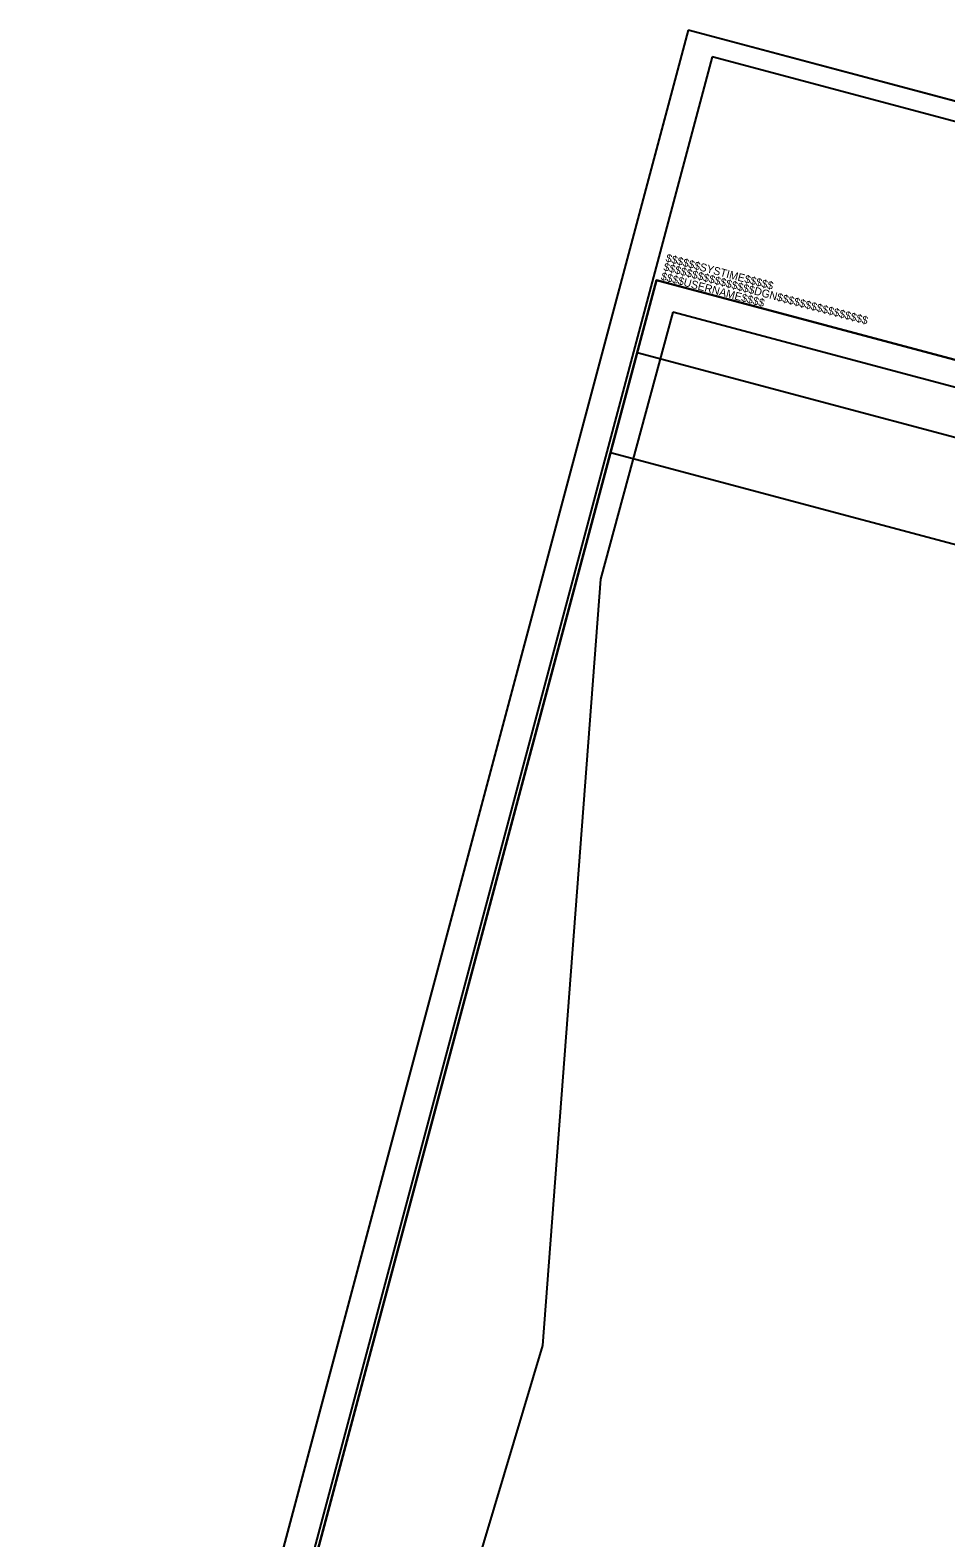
# Model space of a CAD drawing. Extents: x 1782179 to 1783675, y 813964 to 816136.
# Drawn here: x 1782179 to 1782789, y 815050 to 816054 of the extents above; entities that cross this region are included whole.
import ezdxf

# ---------------------------------------------------------------- set-up
doc = ezdxf.new("R2010")
doc.units = 0
for name, color, linetype in [('Sheet Clip Boundary CELL', 7, 'Continuous'), ('Sheet Cutting Line CELL', 7, 'Continuous'), ('Sheet Layout Plan Border', 7, 'Continuous'), ('Sheet Plan CELL', 7, 'Continuous'), ('Sheet Plan Layout CELL', 7, 'Continuous'), ('Sheet Plot Border Inside CELL', 7, 'Continuous'), ('Sheet Plot Border Outside CELL', 7, 'Continuous')]:
    doc.layers.add(name, color=color, linetype=linetype)

msp = doc.modelspace()

# ---------------------------------------------------------------- linework, layer by layer
at = {"layer": 'Sheet Clip Boundary CELL'}
msp.add_lwpolyline([(1782607.1, 815866.5), (1782558.9, 815688.6), (1782520.3, 815177.9), (1782448.8, 814938.8), (1782554.3, 814867.2), (1782519.6, 814798.9), (1782507.5, 814733.2), (1783124.8, 814377.4), (1783147.7, 814463.1), (1783193.9, 814449.4), (1783239.4, 814501.8), (1783298.4, 814452.3), (1783593.6, 815603.4)], close=True, dxfattribs=at)
at = {"layer": 'Sheet Cutting Line CELL'}
for p, q in [((1782617.4, 816054.3), (1782183.6, 814427.7)), ((1783675.4, 815772.2), (1782617.4, 816054.3))]:
    msp.add_line(p, q, dxfattribs=at)
at = {"layer": 'Sheet Layout Plan Border'}
for points in [[(1782596.2, 815887.7), (1782209.7, 814438.3), (1783019.9, 814222.2), (1783071.4, 814415.5), (1783275.8, 814361), (1783610.8, 815617.1)], [(1782583.3, 815839.3), (1782222.6, 814486.6), (1783032.8, 814270.5), (1783081.5, 814453.4), (1783285.9, 814398.9), (1783597.9, 815568.8)]]:
    msp.add_lwpolyline(points, close=True, dxfattribs=at)
at = {"layer": 'Sheet Plan CELL'}
msp.add_line((1782596.2, 815887.7), (1782596.2, 815887.7), dxfattribs=at)
for points in [[(1783224.2, 814167.7), (1783610.8, 815617.1), (1782596.2, 815887.7), (1782209.7, 814438.3)], [(1782596.2, 815887.7), (1783610.7, 815617.1), (1783275.8, 814361), (1783130.8, 814399.7), (1783079.2, 814206.4), (1782209.7, 814438.3)]]:
    msp.add_lwpolyline(points, close=True, dxfattribs=at)
at = {"layer": 'Sheet Plan Layout CELL'}
for points in [[(1783610.7, 815617.1), (1782596.2, 815887.7), (1782209.7, 814438.3), (1783019.9, 814222.2), (1783081.5, 814453.4), (1783285.9, 814398.9)], [(1783580.1, 815502.2), (1782565.6, 815772.8), (1782179.1, 814323.4), (1782989.2, 814107.4), (1783050.9, 814338.5), (1783255.2, 814284)]]:
    msp.add_lwpolyline(points, close=True, dxfattribs=at)
at = {"layer": 'Sheet Plot Border Inside CELL'}
msp.add_lwpolyline([(1782633.3, 816036.6), (1782204.1, 814426.9), (1783223.4, 814155), (1783652.7, 815764.7)], close=True, dxfattribs=at)
at = {"layer": 'Sheet Plot Border Outside CELL'}
msp.add_lwpolyline([(1782617.4, 816054.3), (1782183.6, 814427.7), (1783241.6, 814145.5), (1783675.4, 815772.2)], close=True, dxfattribs=at)

# ---------------------------------------------------------------- texts
at = {"layer": 'Sheet Plan CELL'}
for s, p in [('$$$$$$SYSTIME$$$$$', (1782602, 815900.3)), ('$$$$$$$$$$$$$$$$DGN$$$$$$$$$$$$$$$$', (1782600.5, 815894.4)), ('$$$$USERNAME$$$$', (1782598.8, 815888.1))]:
    msp.add_text(s, height=5.25, rotation=345.0673, dxfattribs=at).set_placement(p)

doc.saveas('drawing.dxf')
